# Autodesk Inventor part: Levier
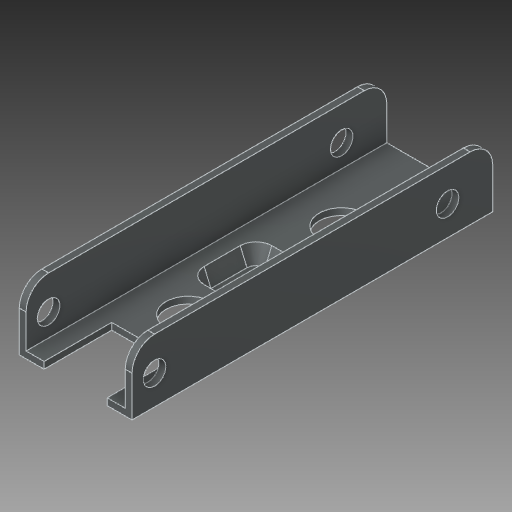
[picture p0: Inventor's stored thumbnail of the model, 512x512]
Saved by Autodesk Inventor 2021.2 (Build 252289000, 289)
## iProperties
Created: 2018-06
Part Number: Levier
Material: Zinc
Document SubType Name: Tôle
Designer: Fabian Perrée
Density: 7 g/cm^3
Appearance: Zinc
Flat Pattern Width: 2.5 cm
Flat Pattern Length: 8 cm
Flat Pattern Area: 20 cm^2
Sheet Metal Rule: Par défaut_mm
Sheet Metal Width: 25,000 mm
Sheet Metal Length: 80,000 mm
Sheet Metal Area: 2000,000 mm^2
Author: Fabian Perrée
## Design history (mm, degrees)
sketch "Esquisse1"
  geometry: L1 (0, 0)-(-12.5, 0); L2 (-12.5, 0)-(-12.5, 14); L3 (-12.5, 14)-(12.5, 14); L4 (12.5, 14)-(12.5, 0); L5 (12.5, 0)-(0, 0)
  constraints: 10 end point, 3 perpendicular, 1 collinear, 1 horizontal, 1 point on line
  dimensions: "d0" = 12.5 distance of L1.start L1.end; "d1" = 14 distance of L1.end L2.end; "d2" = 25 distance of L2.end L3.end (= 2 x d0)
extrude "Extrusion1" new body sketch "Esquisse1" stored distance "d3" = 80; taper "d4" = 0 deg
feature "Coque1" dims "d5" = 1.5
fillet "Congé1" dims "d6" = 5
sketch "Esquisse2"
  geometry: L1 (22, -80)-(0, -80) reference; L2 (4, -80)-(18, -80); L3 (18, -80)-(18, -65); L4 (18, -65)-(4, -65); L5 (4, -65)-(4, -80); L6 (11, -40)-(11, -80); L7 (7, -46)-(15, -46); L8 (17, -44)-(17, -36); L9 (15, -34)-(7, -34); L10 (5, -36)-(5, -44); L11 (3.5, -44)-(3.5, -36); L12 (7, -32.5)-(15, -32.5); L13 (18.5, -36)-(18.5, -44); L14 (15, -47.5)-(7, -47.5); L15 (15, -31.5)-(7, -31.5); L16 (2.5, -36)-(2.5, -44); L17 (7, -48.5)-(15, -48.5); L18 (19.5, -44)-(19.5, -36); A1 r 2 centre (7, -44) between (5, -44) and (7, -46); A2 r 2 centre (7, -36) between (7, -34) and (5, -36); A3 r 2 centre (15, -36) between (17, -36) and (15, -34); A4 r 2 centre (15, -44) between (15, -46) and (17, -44); A5 r 3.5 centre (7, -36) between (7, -32.5) and (3.5, -36); A6 r 3.5 centre (15, -36) between (18.5, -36) and (15, -32.5); A7 r 3.5 centre (15, -44) between (15, -47.5) and (18.5, -44); A8 r 3.5 centre (7, -44) between (3.5, -44) and (7, -47.5); A9 r 4.5 centre (7, -36) between (7, -31.5) and (2.5, -36); A10 r 4.5 centre (7, -44) between (2.5, -44) and (7, -48.5); A11 r 4.5 centre (15, -44) between (15, -48.5) and (19.5, -44); A12 r 4.5 centre (15, -36) between (19.5, -36) and (15, -31.5); 4 further points
  constraints: 34 end point, 24 point on circle, 12 centre point, 8 parallel, 8 tangent, 7 point on line, 5 perpendicular, 3 equal radius, 2 horizontal, 1 midpoint, 1 vertical, 15 other
  dimensions: "d7" = 14 distance of L3.end L4.end; "d8" = 15 distance of L4.end L2.start; "d21" = 30 distance of point (11, -55) point (11, -25); "d22" = 25 distance from line of L1 point (11, -55); "d23" = 12 distance of point (5, -34) point (5, -46); "d24" = 46 distance between parallel lines of L1 L9; "d25" = 2 radius of A1 (derived); "d26" = 1.5 distance between parallel lines of L10 L11; "d57" = 1 distance between parallel lines of L12 L15
extrude "Extrusion2" cut sketch "Esquisse2" extent not by distance; stored distance "d9" = 80; taper "d10" = 0 deg
sketch "Esquisse3"
  geometry: L1 (0, 0)-(0, 9) reference; L2 (0, 0)-(80, 0) reference; 3 further points
  constraints: 1 horizontal alignment
  dimensions: "d11" = 5 distance from line of L1 point (5, 6.5); "d12" = 6.5 distance from line of L2 point (5, 6.5); "d20" = 65 distance of point (5, 6.5) point (70, 6.5)
hole "Perçage1" sketch "Esquisse3" at (5, 6.5), (70, 6.5) diameter "d13" = 5; stored, may be unused: countersink angle "d17" = 90 deg, drill point angle "d19" = 118 deg; dims "d14" = 6, "d15" = 4, "d16" = 2, "d18" = 8
node "Plan de construction1"
sketch "Esquisse4"
  geometry: L1 (5, -36)-(5, -44) reference; L2 (15, -34)-(7, -34) reference; L3 (17, -44)-(17, -36) reference; L4 (7, -46)-(15, -46) reference; A1 r 2 centre (7, -36) between (7, -34) and (5, -36) reference; A2 r 2 centre (15, -36) between (17, -36) and (15, -34) reference; A3 r 2 centre (15, -44) between (15, -46) and (17, -44) reference; A4 r 2 centre (7, -44) between (5, -44) and (7, -46) reference; 1 further point
feature "Lissage2" sketch "Esquisse4" dims "d62" = 0, "d63" = 90 deg, "d64" = 0, "d65" = 90 deg
node "Plan de construction2"
sketch "Esquisse5"
  geometry: L1 (5, -36)-(5, -44) reference; L2 (7, -46)-(15, -46) reference; L3 (17, -44)-(17, -36) reference; L4 (15, -34)-(7, -34) reference; L5 (17, -44)-(18.05, -44) reference; A1 r 2 centre (7, -44) between (5, -44) and (7, -46) reference; A2 r 2 centre (15, -36) between (17, -36) and (15, -34) reference; A3 r 2 centre (7, -36) between (7, -34) and (5, -36) reference; A4 r 2 centre (15, -44) between (15, -46) and (17, -44) reference; A5 r 2 centre (15, -44) between (15, -46) and (17, -44); 1 further point
  constraints: 2 point on circle, 1 centre point, 1 tangent
feature "Lissage3" sketch "Esquisse5" dims "d44" = 0, "d45" = 90 deg, "d66" = 0, "d67" = 90 deg
sketch "Esquisse6"
  geometry: L1 (4, -65)-(18, -65) reference; L2 (22, -80)-(18, -80) reference; L3 (0, 0)-(22, 0) reference; L4 (11, 0)-(11, -65); 3 further points
  constraints: 2 end point, 2 midpoint, 2 point on line
  dimensions: "d48" = 34 distance of point (11, -21) point (11, -55); "d49" = 25 distance from line of L2 point (11, -55)
hole "Perçage2" sketch "Esquisse6" at (11, -55), (11, -21) diameter "d50" = 10; stored, may be unused: countersink angle "d54" = 90 deg, drill point angle "d56" = 118 deg; dims "d51" = 6, "d52" = 4, "d53" = 2, "d55" = 8
node "Solide1"
feature "Définition1"
other parameters: "d27" = -5, "d43" = 1.5, "d58" = 0.5, "d59" = 2, "d60" = 0, "Epaisseur" = 1.5 (derived), "FacteurX" = 4.4, "RayonPli" = 1.5 (= Epaisseur), "LargeurGrugeage" = 1.5 (= Epaisseur), "ProfondeurGrugeage" = 0.75 (= 0.5 x Epaisseur), "TailleGrugeage" = 6 (= 4 x Epaisseur), "JeuJointure" = 0.01, "RestesMinimum" = 3 (= 2 x Epaisseur), "Rayondetransition" = 1.5 (= RayonPli), "TailleRayonJacobi" = 1.5 (= RayonPli), "TailleJeu" = 1.5 (= Epaisseur), "Epaisseur" = 1.5, "LargeurGrugeage" = 1.5, "ProfondeurGrugeage" = 0.75, "RayonPli" = 1.5, "Rayondetransition" = 1.5, "RestesMinimum" = 3, "TailleGrugeage" = 6, "TailleJeu" = 1.5, "TailleRayonJacobi" = 1.5
